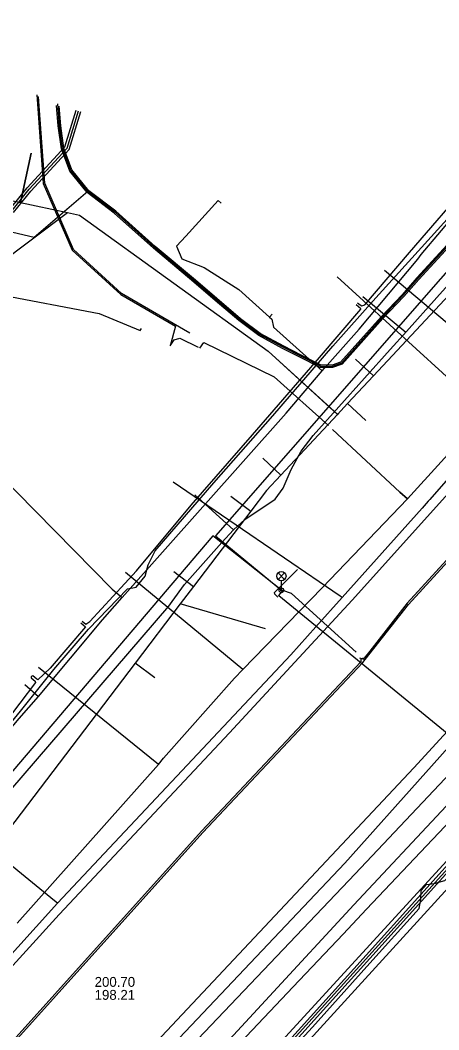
# Model space of a CAD drawing. Extents: x -598932 to -598196, y -1162210 to -1161504.
# Drawn here: x -598473 to -598439.1, y -1161629.7 to -1161548 of the extents above; entities that cross this region are included whole.
import ezdxf

# ---------------------------------------------------------------- set-up
doc = ezdxf.new("R2010")
doc.units = 0
for name, color, linetype in [('Vrstva 1', 7, 'Continuous'), ('Vrstva 12', 7, 'Continuous'), ('Vrstva 14', 7, 'Continuous'), ('Vrstva 16', 7, 'Continuous'), ('Vrstva 33', 7, 'Continuous'), ('Vrstva 4', 7, 'Continuous'), ('Vrstva 42', 7, 'Continuous'), ('Vrstva 44', 7, 'Continuous'), ('Vrstva 52', 7, 'Continuous'), ('Vrstva 53', 7, 'Continuous'), ('Vrstva 54', 7, 'Continuous'), ('Vrstva 55', 7, 'Continuous'), ('Vrstva 58', 7, 'Continuous'), ('Vrstva 9', 7, 'Continuous')]:
    doc.layers.add(name, color=color, linetype=linetype)

msp = doc.modelspace()

# ---------------------------------------------------------------- linework, layer by layer
at = {"layer": 'Vrstva 1'}
for p, q in [((-598472.07, -1161558.76), (-598472.929, -1161562.744)), ((-598475.9, -1161568.64), (-598469.148, -1161563.559)), ((-598453.124, -1161597.256), (-598460.031, -1161595.244))]:
    msp.add_line(p, q, dxfattribs=at)
msp.add_lwpolyline([(-598343.372, -1161505.182), (-598349.192, -1161510.657), (-598372.233, -1161533.783), (-598382.612, -1161544.945), (-598406.057, -1161570.232), (-598441.133, -1161608.511), (-598461.94, -1161630.69)], dxfattribs=at)
at = {"layer": 'Vrstva 12'}
for p, q in [((-598440.54, -1161566.96), (-598435.7, -1161561.21)), ((-598440.81, -1161567.32), (-598440.54, -1161566.96)), ((-598452.8, -1161572.02), (-598452.6, -1161571.78)), ((-598448.55, -1161576.36), (-598448.37, -1161576.16)), ((-598448.37, -1161576.16), (-598447.93, -1161575.66)), ((-598476.18, -1161583.22), (-598465.52, -1161594.05)), ((-598465.52, -1161594.05), (-598464.72, -1161594.72)), ((-598472.59, -1161601.77), (-598471.5, -1161602.74))]:
    msp.add_line(p, q, dxfattribs=at)
for points in [[(-598456.72, -1161562.8), (-598456.95, -1161562.59), (-598459.58, -1161565.47)], [(-598459.58, -1161565.47), (-598460.33, -1161566.29), (-598459.91, -1161567.31), (-598458.1, -1161568.02), (-598455.3, -1161569.8), (-598452.8, -1161572.02)], [(-598447.93, -1161575.66), (-598445.57, -1161572.99), (-598440.81, -1161567.32)], [(-598452.8, -1161572.02), (-598452.62, -1161572.18), (-598452.48, -1161572.83), (-598448.55, -1161576.36)], [(-598464.72, -1161594.72), (-598451.46, -1161579.79), (-598448.55, -1161576.36)], [(-598471.5, -1161602.74), (-598466.31, -1161596.54), (-598464.72, -1161594.72)], [(-598477.7, -1161610.13), (-598476.5, -1161608.59), (-598473.05, -1161604.51), (-598471.5, -1161602.74)], [(-598433.77, -1161610.9), (-598466.88, -1161647.08), (-598467.08, -1161647.64), (-598467.77, -1161648.05), (-598484.01, -1161665.77)]]:
    msp.add_lwpolyline(points, dxfattribs=at)
at = {"layer": 'Vrstva 14'}
for p, q in [((-598471.616, -1161554.17), (-598471.49, -1161554.2)), ((-598470.98, -1161561.19), (-598471.49, -1161554.2)), ((-598468.66, -1161566.56), (-598470.98, -1161561.19)), ((-598464.77, -1161570.12), (-598468.66, -1161566.56)), ((-598459.24, -1161573.32), (-598464.77, -1161570.12))]:
    msp.add_line(p, q, dxfattribs=at)
for points in [[(-598597.949, -1161786.696), (-598594.355, -1161782.22), (-598591.124, -1161778.235), (-598590.488, -1161777.45), (-598568.259, -1161750.324), (-598540.145, -1161717.756), (-598494.895, -1161668.814), (-598474.946, -1161646.048), (-598446.726, -1161616.22), (-598420.512, -1161586.879), (-598391.532, -1161555.529), (-598341.416, -1161505.182)], [(-598378.256, -1161519.804), (-598395.164, -1161537.544), (-598408.344, -1161551.754), (-598412.164, -1161556.015), (-598420.701, -1161565.422), (-598434.416, -1161580.555), (-598439.854, -1161586.796), (-598439.977, -1161586.934), (-598440.475, -1161587.492), (-598446.946, -1161594.711), (-598449.055, -1161597.092)], [(-598434.416, -1161580.555), (-598434.556, -1161580.418), (-598447.351, -1161568.768)], [(-598573.404, -1161732.925), (-598571.604, -1161731.052), (-598554.514, -1161713.376), (-598533.774, -1161691.098), (-598513.523, -1161668.723), (-598504.735, -1161659.069), (-598494, -1161647.223), (-598480.574, -1161632.154), (-598477.858, -1161629.221), (-598469.826, -1161620.401), (-598456.055, -1161605.679), (-598446.117, -1161594.93), (-598428.638, -1161575.491)], [(-598446.946, -1161594.711), (-598447.108, -1161594.603), (-598460.59, -1161585.376)], [(-598449.055, -1161597.092), (-598451.08, -1161599.354), (-598469.948, -1161619.476), (-598481.318, -1161632.069), (-598500.359, -1161653.156), (-598508.903, -1161662.52), (-598516.704, -1161671.085), (-598523.517, -1161678.934), (-598531.97, -1161688.321), (-598542.658, -1161699.746), (-598544.581, -1161701.802), (-598554.215, -1161711.962), (-598572.329, -1161730.54), (-598573.411, -1161730.417), (-598574.926, -1161728.994), (-598576.936, -1161727.101), (-598579.192, -1161727.23), (-598579.92, -1161727.954)], [(-598469.948, -1161619.476), (-598470.196, -1161619.273), (-598482.701, -1161609.06)], [(-598589.947, -1161792.741), (-598577.445, -1161777.792), (-598565.596, -1161764.237), (-598559.546, -1161757.337), (-598558.635, -1161756.275), (-598558.918, -1161751.624), (-598555.314, -1161747.837), (-598550.53, -1161742.727), (-598537.985, -1161729.402), (-598525.355, -1161715.849), (-598512.719, -1161702.199), (-598500.184, -1161688.704), (-598495.944, -1161684.141), (-598496.644, -1161675.242), (-598493.647, -1161671.551), (-598491.273, -1161668.615), (-598474.912, -1161650.419), (-598466.442, -1161641.794), (-598445.99, -1161619.606), (-598438.518, -1161611.629), (-598437.483, -1161610.512)]]:
    msp.add_lwpolyline(points, dxfattribs=at)
at = {"layer": 'Vrstva 16'}
for p, q in [((-598471.62, -1161554.03), (-598471.097, -1161561.199)), ((-598471.097, -1161561.199), (-598468.762, -1161566.604)), ((-598468.762, -1161566.604), (-598464.838, -1161570.195)), ((-598432.96, -1161577.15), (-598443.51, -1161568.25)), ((-598464.838, -1161570.195), (-598460.417, -1161572.753)), ((-598460.417, -1161572.753), (-598460.84, -1161574.35)), ((-598460.84, -1161574.35), (-598460.51, -1161573.86)), ((-598460.51, -1161573.86), (-598460.06, -1161573.72)), ((-598460.06, -1161573.72), (-598458.57, -1161574.47)), ((-598458.45, -1161574.53), (-598458.12, -1161574.07)), ((-598458.12, -1161574.07), (-598452.43, -1161576.87)), ((-598452.43, -1161576.87), (-598448.04, -1161580.79)), ((-598447.72, -1161581.13), (-598442.26, -1161586.19)), ((-598442.26, -1161586.19), (-598441.66, -1161586.74)), ((-598454.96, -1161600.54), (-598464.44, -1161592.69)), ((-598461.78, -1161608.24), (-598471.48, -1161600.39))]:
    msp.add_line(p, q, dxfattribs=at)
for points in [[(-598473.2, -1161621.09), (-598461.78, -1161608.24), (-598461.37, -1161607.74), (-598455.64, -1161601.25), (-598454.96, -1161600.54), (-598448.54, -1161593.94), (-598441.66, -1161586.74), (-598432.96, -1161577.15), (-598421.13, -1161564.15), (-598392.87, -1161534.27), (-598377.76, -1161518.29), (-598376.98, -1161517.48), (-598363.01, -1161531.33), (-598362.8, -1161531.54)], [(-598386.81, -1161556.37), (-598393.69, -1161563.71), (-598398.11, -1161568.49), (-598402.48, -1161573.4), (-598413.33, -1161585.48), (-598419.6, -1161592.5), (-598422.55, -1161595.77), (-598427.36, -1161601.01), (-598427.63, -1161601.31), (-598432.34, -1161606.44), (-598433.05, -1161607.34), (-598433.36, -1161607.68), (-598434.26, -1161608.65), (-598444.97, -1161619.96), (-598446.86, -1161621.99), (-598450.89, -1161626.24), (-598466.05, -1161642.27)], [(-598441.66, -1161586.74), (-598442.26, -1161586.19), (-598447.72, -1161581.13)]]:
    msp.add_lwpolyline(points, dxfattribs=at)
at = {"layer": 'Vrstva 33'}
for p, q in [((-598452.115, -1161592.725), (-598451.585, -1161593.255)), ((-598452.115, -1161593.255), (-598451.585, -1161592.725)), ((-598451.85, -1161594.14), (-598451.85, -1161593.365))]:
    msp.add_line(p, q, dxfattribs=at)
for centre, radius in [((-598451.85, -1161592.99), 0.375), ((-598451.85, -1161594.14), 0.19), ((-598451.85, -1161594.14), 0.05)]:
    msp.add_circle(centre, radius, dxfattribs=at)
at = {"layer": 'Vrstva 42'}
for p, q in [((-598469.36, -1161558.25), (-598468.446, -1161555.272)), ((-598469.182, -1161558.353), (-598468.255, -1161555.331)), ((-598469.005, -1161558.456), (-598468.064, -1161555.39)), ((-598469.36, -1161558.25), (-598472.4, -1161561.55)), ((-598469.182, -1161558.353), (-598472.246, -1161561.678)), ((-598469.005, -1161558.456), (-598472.106, -1161561.822)), ((-598473.75, -1161563.22), (-598472.4, -1161561.55)), ((-598473.625, -1161563.385), (-598472.246, -1161561.678)), ((-598473.505, -1161563.553), (-598472.106, -1161561.822))]:
    msp.add_line(p, q, dxfattribs=at)
for points in [[(-598514.881, -1161675.495), (-598514.586, -1161675.706), (-598514.544, -1161675.66), (-598509.789, -1161670.451), (-598509.79, -1161670.452), (-598495.271, -1161654.682), (-598493.794, -1161653.11), (-598482.467, -1161640.638), (-598481.951, -1161640.136), (-598458.21, -1161613.742), (-598445.27, -1161599.978), (-598445.069, -1161599.756), (-598441.565, -1161595.287), (-598431.149, -1161583.871), (-598378.675, -1161526.796), (-598362.821, -1161511.358), (-598362.827, -1161511.253), (-598362.686, -1161511.241), (-598356.249, -1161505.182)], [(-598514.881, -1161675.495), (-598514.586, -1161675.706), (-598514.544, -1161675.66), (-598509.789, -1161670.451), (-598509.79, -1161670.452), (-598495.271, -1161654.682), (-598493.794, -1161653.11), (-598482.467, -1161640.638), (-598481.951, -1161640.136), (-598458.21, -1161613.742), (-598445.27, -1161599.978), (-598445.069, -1161599.756), (-598441.565, -1161595.287), (-598431.149, -1161583.871), (-598378.675, -1161526.796), (-598362.821, -1161511.358), (-598362.827, -1161511.253), (-598362.686, -1161511.241), (-598356.249, -1161505.182)], [(-598482.615, -1161640.14), (-598481.951, -1161640.136), (-598458.21, -1161613.742), (-598445.27, -1161599.978), (-598445.069, -1161599.756), (-598441.565, -1161595.287), (-598431.149, -1161583.871), (-598378.675, -1161526.796), (-598362.821, -1161511.358), (-598362.827, -1161511.253), (-598362.686, -1161511.241), (-598356.249, -1161505.182)], [(-598445.533, -1161599.605), (-598445.069, -1161599.756), (-598441.565, -1161595.287), (-598431.149, -1161583.871), (-598378.675, -1161526.796), (-598362.821, -1161511.358), (-598362.827, -1161511.253), (-598362.686, -1161511.241), (-598356.249, -1161505.182)], [(-598476.465, -1161608.22), (-598472.955, -1161603.94), (-598470.26, -1161600.54), (-598467.44, -1161597.3), (-598464.29, -1161594.03), (-598463.6, -1161593.88), (-598462.87, -1161593), (-598462.63, -1161592.07), (-598462.06, -1161590.94), (-598457.31, -1161585.43), (-598452.529, -1161580.011), (-598447.689, -1161574.381), (-598444.21, -1161570.46), (-598441.3, -1161567.26), (-598435.08, -1161560.38), (-598431.65, -1161556.3), (-598428.06, -1161552.41), (-598423.96, -1161548), (-598423.74, -1161547.69)], [(-598445.688, -1161570.879), (-598445.492, -1161571.041), (-598445.34, -1161571.11), (-598445.09, -1161571.04), (-598441.5, -1161566.79), (-598436.51, -1161561.02), (-598433.4, -1161557.329), (-598433.849, -1161556.964)], [(-598387.283, -1161560.772), (-598388.983, -1161562.562), (-598395.611, -1161569.76), (-598395.999, -1161570.127), (-598396.197, -1161570.368), (-598399.938, -1161574.427), (-598406.758, -1161581.798), (-598417.087, -1161593.013), (-598421.217, -1161597.515), (-598421.344, -1161598.244), (-598421.49, -1161599.08), (-598421.65, -1161599.23), (-598422.7, -1161600.27), (-598423.08, -1161600.65), (-598423.5, -1161601.06), (-598424.039, -1161601.179), (-598424.72, -1161601.33), (-598432.474, -1161609.755), (-598445.008, -1161623.694), (-598461.236, -1161641.709)], [(-598467.947, -1161596.634), (-598467.668, -1161596.87), (-598467.34, -1161596.67), (-598463.57, -1161592.56), (-598459.15, -1161587.25), (-598454.19, -1161581.56), (-598448.76, -1161575.29), (-598445.43, -1161571.38), (-598445.426, -1161571.357), (-598445.816, -1161571.034)], [(-598406.04, -1161581.87), (-598407.62, -1161583.94), (-598408.397, -1161584.168), (-598416.793, -1161593.283), (-598421.344, -1161598.244), (-598423.305, -1161600.382), (-598424.039, -1161601.179), (-598432.178, -1161610.025), (-598444.71, -1161623.962), (-598460.94, -1161641.979), (-598483.892, -1161666.804), (-598490.009, -1161673.693), (-598489.744, -1161674.222), (-598490.288, -1161673.987), (-598492.973, -1161677.375), (-598495.513, -1161681.565), (-598498.183, -1161687.257), (-598495.776, -1161690.441)], [(-598431.26, -1161583.77), (-598441.68, -1161595.19), (-598444.698, -1161599.071), (-598445.156, -1161599.624), (-598445.433, -1161599.698)], [(-598452.138, -1161594.688), (-598452.37, -1161594.45), (-598452.404, -1161594.306), (-598450.543, -1161592.451)], [(-598445.791, -1161599.159), (-598451.03, -1161594.39), (-598451.74, -1161594.17), (-598452.1, -1161594.58)], [(-598445.791, -1161599.159), (-598451.03, -1161594.39), (-598451.74, -1161594.17), (-598452.1, -1161594.58)], [(-598445.791, -1161599.159), (-598451.03, -1161594.39), (-598451.74, -1161594.17), (-598452.1, -1161594.58)], [(-598468.077, -1161596.787), (-598467.695, -1161597.11), (-598470.55, -1161600.45), (-598471.53, -1161601.39), (-598471.634, -1161601.344), (-598471.955, -1161601.07), (-598472.073, -1161601.107), (-598472.084, -1161601.226), (-598471.768, -1161601.505), (-598471.73, -1161601.61), (-598475.56, -1161606.62), (-598476.142, -1161607.28)], [(-598445.433, -1161599.698), (-598445.423, -1161599.921), (-598458.32, -1161613.64), (-598482.063, -1161640.036), (-598482.553, -1161640.291)]]:
    msp.add_lwpolyline(points, dxfattribs=at)
at = {"layer": 'Vrstva 44'}
for points in [[(-598435.845, -1161563.626), (-598440.745, -1161568.977), (-598441.946, -1161570.347), (-598443.646, -1161572.138), (-598446.942, -1161575.836), (-598447.723, -1161576.11), (-598448.724, -1161576.1), (-598450.345, -1161575.279), (-598451.757, -1161574.559), (-598453.674, -1161573.524), (-598455.293, -1161572.308), (-598457.205, -1161570.676), (-598458.925, -1161569.196), (-598462.196, -1161566.445), (-598465.364, -1161563.597), (-598467.56, -1161561.932), (-598468.958, -1161560.21), (-598469.638, -1161558.405), (-598469.889, -1161556.551), (-598470.022, -1161554.904)], [(-598435.995, -1161563.494), (-598440.894, -1161568.843), (-598442.094, -1161570.213), (-598443.794, -1161572.002), (-598447.058, -1161575.664), (-598447.757, -1161575.91), (-598448.676, -1161575.9), (-598450.255, -1161575.101), (-598451.664, -1161574.381), (-598453.566, -1161573.356), (-598455.167, -1161572.152), (-598457.075, -1161570.524), (-598458.795, -1161569.044), (-598462.064, -1161566.295), (-598465.236, -1161563.443), (-598467.42, -1161561.788), (-598468.782, -1161560.11), (-598469.443, -1161558.355), (-598469.691, -1161556.529), (-598469.818, -1161554.955)]]:
    msp.add_lwpolyline(points, dxfattribs=at)
at = {"layer": 'Vrstva 52'}
msp.add_lwpolyline([(-598382.98, -1161519.06), (-598365.39, -1161539.3), (-598398.68, -1161574.69), (-598431.92, -1161611.17), (-598468.58, -1161651.39), (-598447.43, -1161669.94)], dxfattribs=at)
at = {"layer": 'Vrstva 53'}
for points in [[(-598420.52, -1161547.12), (-598424.44, -1161551.14), (-598425.78, -1161552.1), (-598427.69, -1161553.97), (-598428.88, -1161555.35), (-598430.23, -1161556.94), (-598435.92, -1161563.56), (-598440.82, -1161568.91), (-598442.02, -1161570.28), (-598443.72, -1161572.07), (-598447, -1161575.75), (-598447.74, -1161576.01), (-598448.7, -1161576), (-598451.71, -1161574.47), (-598453.62, -1161573.44), (-598455.23, -1161572.23), (-598457.14, -1161570.6), (-598458.86, -1161569.12), (-598462.13, -1161566.37), (-598465.3, -1161563.52), (-598467.49, -1161561.86)], [(-598467.49, -1161561.86), (-598471.845, -1161565.591), (-598526.69, -1161552.71)], [(-598467.49, -1161561.86), (-598468.87, -1161560.16), (-598469.54, -1161558.38), (-598469.79, -1161556.54), (-598469.933, -1161554.77)]]:
    msp.add_lwpolyline(points, dxfattribs=at)
at = {"layer": 'Vrstva 54'}
msp.add_line((-598452.066, -1161594.557), (-598431.867, -1161611.127), dxfattribs=at)
at = {"layer": 'Vrstva 55'}
for p, q in [((-598482.52, -1161568.71), (-598466.58, -1161571.73)), ((-598466.58, -1161571.73), (-598463.28, -1161573.1)), ((-598463.28, -1161573.1), (-598463.16, -1161572.94))]:
    msp.add_line(p, q, dxfattribs=at)
for points in [[(-598593.724, -1161815.599), (-598601.79, -1161825.2), (-598612.66, -1161816.58), (-598605.21, -1161808.89), (-598597.75, -1161800.73), (-598596.12, -1161801.43), (-598593.55, -1161803.29), (-598583.76, -1161792.8), (-598587.73, -1161788.84), (-598556.49, -1161751.54), (-598543.66, -1161733.82), (-598504.5, -1161691.15), (-598500.07, -1161684.86), (-598483.28, -1161665.74), (-598469.525, -1161651.138), (-598469.135, -1161651.28), (-598469.525, -1161651.138), (-598431.76, -1161609.32), (-598365.821, -1161539.037), (-598342.93, -1161515.615), (-598331.661, -1161505.182)], [(-598402.127, -1161505.182), (-598389.64, -1161508.67), (-598391.671, -1161515.864), (-598383.066, -1161519.277), (-598391.671, -1161515.864), (-598393.76, -1161520.96), (-598414.51, -1161541.48), (-598422.48, -1161550.58), (-598416.91, -1161555.69), (-598422.48, -1161550.58), (-598432.92, -1161562), (-598457.17, -1161589.74), (-598451.81, -1161594.17), (-598457.4, -1161589.74), (-598474.66, -1161610.02)], [(-598468.56, -1161651.3), (-598468.8, -1161650.92), (-598468.2, -1161650.22), (-598462, -1161643.38), (-598455.58, -1161636.34), (-598449.33, -1161629.52), (-598444.94, -1161624.6), (-598440.7, -1161619.91), (-598440.57, -1161619.18), (-598440.56, -1161618.45), (-598440.13, -1161617.97), (-598439.49, -1161617.87), (-598438.64, -1161617.64), (-598435.93, -1161614.67), (-598433.69, -1161612.19), (-598432.15, -1161610.42), (-598429.39, -1161607.17), (-598429.06, -1161607.01), (-598428.45, -1161607.4)]]:
    msp.add_lwpolyline(points, dxfattribs=at)
at = {"layer": 'Vrstva 58'}
for p, q in [((-598445.251, -1161570.357), (-598441.779, -1161573.236)), ((-598455.72, -1161589.25), (-598458.85, -1161586.42))]:
    msp.add_line(p, q, dxfattribs=at)
for points in [[(-598441.73, -1161573.18), (-598439.28, -1161570.43), (-598434.27, -1161564.84), (-598432.3, -1161563.14), (-598430.11, -1161559.72), (-598427.76, -1161557.7)], [(-598455.72, -1161589.25), (-598454.81, -1161588.4), (-598452.35, -1161586.75), (-598451.71, -1161585.88), (-598451.06, -1161584.36), (-598450.24, -1161582.87), (-598449.27, -1161581.6), (-598443.06, -1161574.64), (-598441.73, -1161573.18)], [(-598460.68, -1161595.06), (-598459.69, -1161593.67), (-598456.66, -1161590.27), (-598455.72, -1161589.25)], [(-598475.64, -1161612.58), (-598474.91, -1161611.65), (-598460.94, -1161595.42), (-598460.68, -1161595.06)]]:
    msp.add_lwpolyline(points, dxfattribs=at)
at = {"layer": 'Vrstva 9'}
for p, q in [((-598472.929, -1161562.744), (-598472.07, -1161558.76)), ((-598468.17, -1161563.77), (-598452.93, -1161574.77)), ((-598452.93, -1161574.77), (-598447.306, -1161579.899)), ((-598452.93, -1161574.77), (-598447.255, -1161579.945)), ((-598445.861, -1161575.42), (-598444.399, -1161576.785)), ((-598445.032, -1161580.394), (-598446.494, -1161579.029)), ((-598453.362, -1161583.453), (-598451.9, -1161584.818)), ((-598455.923, -1161586.524), (-598454.33, -1161587.733)), ((-598460.548, -1161592.617), (-598458.955, -1161593.826)), ((-598462.072, -1161601.24), (-598463.665, -1161600.031)), ((-598437.199, -1161607.856), (-598445.884, -1161617.098)), ((-598445.884, -1161617.098), (-598473.83, -1161646.5))]:
    msp.add_line(p, q, dxfattribs=at)
for points in [[(-598412.76, -1161542.91), (-598414.031, -1161544.271), (-598415.581, -1161545.93), (-598423.28, -1161554.174), (-598424.106, -1161555.058), (-598426.856, -1161558.003), (-598429.232, -1161560.547), (-598434.406, -1161566.086), (-598437.832, -1161569.755), (-598438.276, -1161570.23), (-598444.399, -1161576.785), (-598446.494, -1161579.029), (-598447.306, -1161579.899), (-598451.9, -1161584.818), (-598453.06, -1161586.06)], [(-598484.03, -1161560.35), (-598472.929, -1161562.744), (-598469.148, -1161563.559), (-598468.17, -1161563.77)], [(-598453.06, -1161586.06), (-598454.33, -1161587.733), (-598458.955, -1161593.826), (-598460.031, -1161595.244), (-598463.665, -1161600.031), (-598473.919, -1161613.54), (-598474.838, -1161614.751), (-598475.63, -1161615.794), (-598476.736, -1161617.252), (-598478.9, -1161620.104), (-598478.906, -1161620.112), (-598482.26, -1161624.53)]]:
    msp.add_lwpolyline(points, dxfattribs=at)

# ---------------------------------------------------------------- texts
at = {"layer": 'Vrstva 4'}
for s, p in [('200.70', (-598466.947, -1161626.245)), ('198.21', (-598466.947, -1161627.295))]:
    msp.add_text(s, height=0.8, dxfattribs=at).set_placement(p)

doc.saveas('drawing.dxf')
